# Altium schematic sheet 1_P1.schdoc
size 309 x 223 mm
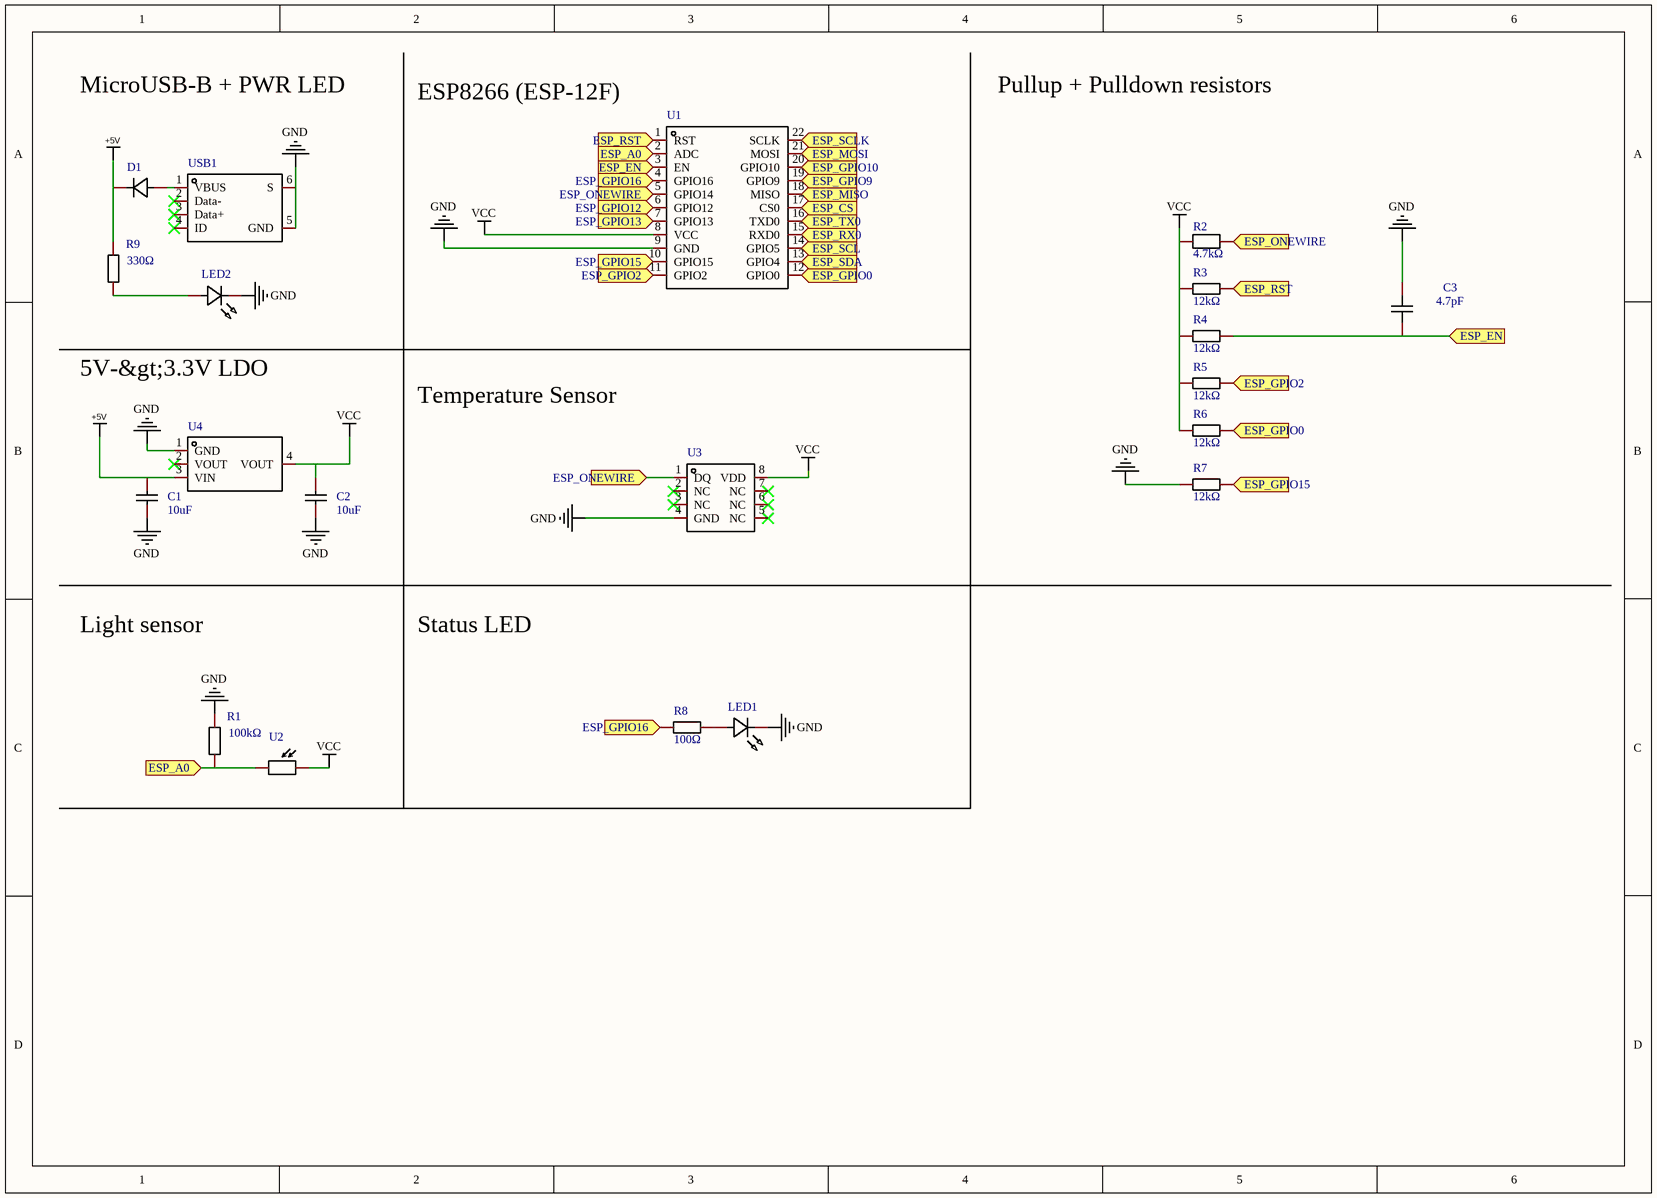
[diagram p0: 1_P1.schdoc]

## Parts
C1  value 10uF  [C0603]  (hidden comment: CL10A106MO8NQNC)
C2  value 10uF  [C0603]  (hidden comment: CL10A106MO8NQNC)
C3  value 4.7pF  [C0603]  (hidden comment: CC0603CRNPO9BN4R7)
D1  1N4007  [SMA_L4.3-W2.5-LS5.0-RD]  (value not drawn)
LED1  XL-1608SURC-06  [LED0603-RD_RED]  (value not drawn)
LED2  XL-1608SURC-06  [LED0603-RD_RED]  (value not drawn)
R1  value 100kΩ  [R0603]  (hidden comment: RC0603FR-07100KL)
R2  Name: 4.7kΩ  [R0603]  (hidden comment: FRC0603J472 TS)
R3  value 12kΩ  [R0603]  (hidden comment: RC0603FR-0712KL)
R4  value 12kΩ  [R0603]  (hidden comment: RC0603FR-0712KL)
R5  value 12kΩ  [R0603]  (hidden comment: RC0603FR-0712KL)
R6  value 12kΩ  [R0603]  (hidden comment: RC0603FR-0712KL)
R7  value 12kΩ  [R0603]  (hidden comment: RC0603FR-0712KL)
R8  value 100Ω  [R0603]  (hidden comment: RC0603FR-07100RL)
R9  value 330Ω  [R0603]  (hidden comment: RC0603FR-07330RL)
U1  ESP-12F(ESP8266MOD)  [WIFIM-SMD_ESP-12F-ESP8266MOD]  (value not drawn)
U2  GT36549  [RES-SMD_L3.6-W2.4]  (value not drawn)
U3  DS18B20U  [MSOP-8_L3.0-W3.0-P0.65-LS4.9-BL]  (value not drawn)
U4  AMS1117-3.3V  [SOT-223_L6.5-W3.5-P2.30-LS7.0-BR]  (value not drawn)
USB1  10118192-0001LF  [MICRO-USB-SMD_10118192-0001LF_1]  (value not drawn)

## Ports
ESP_A0 (in), ESP_CS (in), ESP_EN (in), ESP_GPIO0 (in), ESP_GPIO2 (in), ESP_GPIO9 (in), ESP_GPIO10 (in), ESP_GPIO12 (in), ESP_GPIO13 (in), ESP_GPIO15 (in), ESP_GPIO16 (in), ESP_MISO (in), ESP_MOSI (in), ESP_ONEWIRE (in), ESP_RST (in), ESP_RX0 (in), ESP_SCL (in), ESP_SCLK (in), ESP_SDA (in), ESP_TX0 (in)

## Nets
+5V: C1.2 D1.1(K) R9.2 U4.3(VIN)
GND: C1.1 C2.1 C3.2 LED1.1(K) LED2.1(K) R1.2 R7.1 U1.9(GND) U3.4(GND) U4.1(GND) USB1.5(GND) USB1.6(S)
VCC: C2.2 R2.2 R3.1 R4.1 R5.1 R6.1 U1.8(VCC) U2.2 U3.8(VDD) U4.4(VOUT)
ESP_A0: R1.1 U1.2(ADC) U2.1 ; port ESP_A0
ESP_CS: U1.17(CS0) ; port ESP_CS
ESP_EN: C3.1 R4.2 U1.3(EN) ; port ESP_EN
ESP_GPIO0: R6.2 U1.12(GPIO0) ; port ESP_GPIO0
ESP_GPIO2: R5.2 U1.11(GPIO2) ; port ESP_GPIO2
ESP_GPIO9: U1.19(GPIO9) ; port ESP_GPIO9
ESP_GPIO10: U1.20(GPIO10) ; port ESP_GPIO10
ESP_GPIO12: U1.6(GPIO12) ; port ESP_GPIO12
ESP_GPIO13: U1.7(GPIO13) ; port ESP_GPIO13
ESP_GPIO15: R7.2 U1.10(GPIO15) ; port ESP_GPIO15
ESP_GPIO16: R8.1 U1.4(GPIO16) ; port ESP_GPIO16
ESP_MISO: U1.18(MISO) ; port ESP_MISO
ESP_MOSI: U1.21(MOSI) ; port ESP_MOSI
ESP_ONEWIRE: R2.1 U1.5(GPIO14) U3.1(DQ) ; port ESP_ONEWIRE
ESP_RST: R3.2 U1.1(RST) ; port ESP_RST
ESP_RX0: U1.15(RXD0) ; port ESP_RX0
ESP_SCL: U1.14(GPIO5) ; port ESP_SCL
ESP_SCLK: U1.22(SCLK) ; port ESP_SCLK
ESP_SDA: U1.13(GPIO4) ; port ESP_SDA
ESP_TX0: U1.16(TXD0) ; port ESP_TX0
NetD1_2: D1.2(A) USB1.1(VBUS)
NetLED1_2: LED1.2(A) R8.2
NetLED2_2: LED2.2(A) R9.1

Not connected (* = marked no-connect by the designer): U3 2(NC)* 3(NC)* 5(NC)* 6(NC)* 7(NC)*; U4 2(VOUT)*; USB1 2(Data-)* 3(Data+)* 4(ID)*

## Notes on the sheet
- MicroUSB-B + PWR LED
- ESP8266 (ESP-12F)
- Pullup + Pulldown resistors
- 5V-&gt;3.3V LDO
- Temperature Sensor
- Light sensor
- Status LED

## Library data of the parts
C1 C2 = CL10A106MO8NQNC: Capacitance: Tolerance:±20% Tolerance:±20% Voltage Rated: Temperature Coefficient:; Manufacturer: SAMSUNG(三星); Add into BOM: yes; Tolerance: ±20%; NAME: 2; Pin Type: IN
C3 = CC0603CRNPO9BN4R7: Temperature Coefficient: Tolerance: Tolerance: Body Length:- Body Width:- Body Thickness:- Capacitance: Voltage Rated:; Manufacturer: YAGEO(国巨); Add into BOM: yes; NAME: 2; Pin Type: IN
D1 = 1N4007: Diode Configuration: Reverse Voltage (Vr): Average Rectified Current (Io): Forward Voltage (Vf@If):1.1V@1A Reverse Leakage Current:5A@1kV; Manufacturer: TWGMC(台湾迪嘉); Symbol: 1N4007_C727081; Add into BOM: yes; Reverse Leakage Current: 5A@1kV; NAME: K; NUMBER: 1; Pin Type: IN
LED1 LED2 = XL-1608SURC-06: Manufacturer: XINGLIGHT(成兴光); Add into BOM: yes; NAME: A; NUMBER: 2; Pin Type: IN
R1 = RC0603FR-07100KL: Type:Thick Film Resistors Resistance: Tolerance:±1% Tolerance:±1% Power(Watts): Temperature Coefficient:±100ppm/ Temperature Coefficient:±100ppm/ Overload Voltage (Max): Operating Temperature Range:-55~+155 Operating Temperature Range:-55~+155; Manufacturer: YAGEO(国巨); Add into BOM: yes; Tolerance: ±1%; NAME: 1; Pin Type: IN
R2 = FRC0603J472 TS: Manufacturer: FOJAN(富捷); Add into BOM: yes; NAME: 1; Pin Type: IN
R3-R7 = RC0603FR-0712KL: Type:Thick Film Resistors Resistance: Tolerance: Power(Watts): Temperature Coefficient: Temperature Coefficient: Overload Voltage (Max): Operating Temperature Range: Operating Temperature Range:; Manufacturer: YAGEO(国巨); Add into BOM: yes; NAME: 1; Pin Type: IN
R8 = RC0603FR-07100RL: Type:Thick Film Resistors Resistance: Tolerance: Power(Watts): Temperature Coefficient: Temperature Coefficient: Overload Voltage (Max): Operating Temperature Range: Operating Temperature Range:; Manufacturer: YAGEO(国巨); Add into BOM: yes; NAME: 1; Pin Type: IN
R9 = RC0603FR-07330RL: Type:Thick Film Resistors Resistance: Tolerance:±1% Tolerance:±1% Power(Watts): Temperature Coefficient:±100ppm/ Temperature Coefficient:±100ppm/ Overload Voltage (Max): Operating Temperature Range:-55~+155 Operating Temperature Range:-55~+155; Manufacturer: YAGEO(国巨); Add into BOM: yes; Tolerance: ±1%; NAME: 1; Pin Type: IN
U1 = ESP-12F(ESP8266MOD): Manufacturer: Ai-Thinker(安信可); Add into BOM: yes; Pin Type: IN
U2 = GT36549: Manufacturer: JCHL(晶创和立); Add into BOM: yes; NAME: 2; Pin Type: IN
U3 = DS18B20U: Sensor Type:- Output Type:- Sensing Temperature-Local:- Sensing Temperature-remote:- Resolution:- Features:- Voltage-Supply:- Accuracy-Highest(lowest):- Operating Temperature:-; Manufacturer: UMW(友台半导体); Add into BOM: yes; Pin Type: IN
U4 = AMS1117-3.3V: Output Type:固定 Output Polarity:正 Number of Outputs:1 Maximum Input Voltage:12V Output Voltage:3.3V Output Voltage:3.3V Dropout Voltage:1.5V@(700mA) Output Current:800mA Power Supply Rejection Ratio (PSRR):75dB@(10kHz); Manufacturer: FM富满; Symbol: SC1117-3.3V; Add into BOM: yes; Output Type: 固定; Output Polarity: 正; Number of Outputs: 1; Maximum Input Voltage: 12V; Output Voltage: 3.3V; Output Current: 800mA; Pin Type: IN
USB1 = 10118192-0001LF: Connector Type:Micro-B Standard:USB 2.0 Gender:母座 Number of Contacts:5 Number of Ports:1 Mounting Style:卧贴 Current Rating - Power (Max):- Operating Temperature Range:- Operating Temperature Range:-; Manufacturer: Amphenol; Add into BOM: yes; Gender: 母座; Number of Contacts: 5; Number of Ports: 1; Pin Type: IN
